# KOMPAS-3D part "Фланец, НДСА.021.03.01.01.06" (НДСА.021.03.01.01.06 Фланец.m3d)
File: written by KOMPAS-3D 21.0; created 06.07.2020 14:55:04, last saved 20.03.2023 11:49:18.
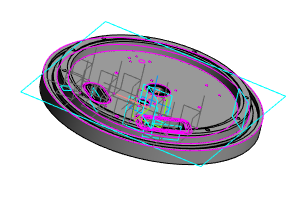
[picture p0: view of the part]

Document properties: Автор: 111; Полное имя файла: C:\Users\korychko\Desktop\PLM\НДСА.021.03.01.01.06 Фланец.m3d

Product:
- Part/product: Фланец  | designation НДСА.021.03.01.01.06
    Материал: АМг2,5 ГОСТ 4784-97 (density 2680 kg/m3)
    Масса: 6.75238
    additional columns: <item xmlns="http://appius.ru/pdm" xmlns:xs="http://www.w3.org/2001/XMLSchema" x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; <item xmlns="http://appius.ru/pdm" xmlns:xs="http://www.w3.org/2001/XMLSchema" x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; <item xmlns="http://appius.ru/pdm" xmlns:xs="http://www.w3.org/2001/XMLSchema" x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; <item xmlns="http://appius.ru/pdm" xmlns:xs="http://www.w3.org/2001/XMLSchema" x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; <item xmlns="http://appius.ru/pdm" xmlns:xs="http://www.w3.org/2001/XMLSchema" x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; <item xmlns="http://appius.ru/pdm" xmlns:xs="http://www.w3.org/2001/XMLSchema" x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; <item xmlns="http://appius.ru/pdm" xmlns:xs="http://www.w3.org/2001/XMLSchema" x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
    source file: НДСА.021.03.01.01.06 Фланец.cdw

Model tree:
1. Эскиз:1
2. Элемент выдавливания:1
     Расстояние 1 = 25
3. Эскиз:3  (with: Элемент выдавливания:1)
4. Элемент выдавливания:3  (with: Элемент выдавливания:1)
     Расстояние 2 = 25
5. Эскиз:4  (with: Элемент выдавливания:1, Элемент выдавливания:3)
6. Элемент выдавливания:4  (with: Элемент выдавливания:1)
     Расстояние 2 = 25
7. Эскиз:6  (with: Элемент выдавливания:1, Элемент выдавливания:3)
8. Элемент выдавливания:5
     Расстояние 2 = 15
9. Условное изображение резьбы:1  (with: Элемент выдавливания:5)  (labels: M4; cil0_24705-2004 coarse)
     Длина резьбы = 15; Шаг резьбы = 0.7; Номинальный диаметр резьбы = 4
10. Подгонка:1  (with: Элемент выдавливания:5)
11. Условное изображение резьбы:2  (with: Элемент выдавливания:5)  (labels: M4; cil0_24705-2004 coarse)
     Длина резьбы = 15; Шаг резьбы = 0.7; Номинальный диаметр резьбы = 4
12. Подгонка:2  (with: Элемент выдавливания:5)
13. Условное изображение резьбы:3  (with: Элемент выдавливания:5)  (labels: M4; cil0_24705-2004 coarse)
     Длина резьбы = 15; Шаг резьбы = 0.7; Номинальный диаметр резьбы = 4
14. Подгонка:3  (with: Элемент выдавливания:5)
15. Условное изображение резьбы:4  (with: Элемент выдавливания:5)  (labels: M4; cil0_24705-2004 coarse)
     Длина резьбы = 15; Шаг резьбы = 0.7; Номинальный диаметр резьбы = 4
16. Подгонка:4  (with: Элемент выдавливания:5)
17. Эскиз:7  (with: Элемент выдавливания:1, Элемент выдавливания:4)
18. Элемент выдавливания:6
     Расстояние 2 = 10
19. Условное изображение резьбы:5  (with: Элемент выдавливания:6)  (labels: M4; cil0_24705-2004 coarse)
     Длина резьбы = 10; Шаг резьбы = 0.7; Номинальный диаметр резьбы = 4
20. Подгонка:5  (with: Элемент выдавливания:6)
21. Смещенная плоскость:1
     Расстояние = 18
22. Эскиз:8  (with: Элемент выдавливания:3)
23. Элемент вращения:2  (with: Элемент выдавливания:3)
     Угол 1 = 360
24. Скругление:3  (with: Элемент вращения:2)
     Радиус = 0.38
25. Скругление:4  (with: Элемент вращения:2)
     Радиус = 0.79
26. Смещенная плоскость:2
     Расстояние = 36
27. Эскиз:9
28. Элемент вращения:3  (with: Элемент выдавливания:4)
     Угол 1 = 360
29. Скругление:5  (with: Элемент вращения:3)
     Радиус = 0.13
30. Скругление:6  (with: Элемент вращения:3)
     Радиус = 0.4
31. Эскиз:10  (with: Элемент выдавливания:1)
32. Элемент выдавливания:7  (with: Элемент выдавливания:1)
     Расстояние 2 = 25
33. Эскиз:11  (with: Элемент выдавливания:1, Элемент выдавливания:7)
34. Элемент выдавливания:8
     Расстояние 2 = 5
35. Смещенная плоскость:3  (with: Элемент выдавливания:7)
     Расстояние = 8.5
36. Эскиз:12  (with: Элемент выдавливания:7)
37. Эскиз:13  (with: Элемент выдавливания:1, Элемент выдавливания:7)
38. Элемент по траектории:1
39. Скругление:7  (with: Элемент по траектории:1)
     Радиус = 0.38
40. Скругление:8  (with: Элемент по траектории:1)
     Радиус = 0.79
41. Эскиз:14  (with: Элемент выдавливания:1)
42. Элемент выдавливания:9  (with: Элемент выдавливания:1)
     Расстояние 2 = 25
43. Эскиз:15  (with: Элемент выдавливания:1, Элемент выдавливания:9)
44. Элемент выдавливания:10
     Расстояние 2 = 5
45. Смещенная плоскость:4  (with: Элемент выдавливания:9)
     Расстояние = 15
46. Эскиз:16  (with: Элемент выдавливания:9)
47. Эскиз:17  (with: Элемент выдавливания:1, Элемент выдавливания:9)
48. Элемент по траектории:2
49. Скругление:9  (with: Элемент по траектории:2)
     Радиус = 0.38
50. Скругление:10  (with: Элемент по траектории:2)
     Радиус = 0.79
51. Эскиз:19  (with: Элемент выдавливания:1, Скругление:3)
52. Элемент выдавливания:12
     Расстояние 2 = 12
53. Условное изображение резьбы:14  (with: Элемент выдавливания:12)  (labels: M6; cil0_24705-2004 coarse)
     Длина резьбы = 12; Шаг резьбы = 1; Номинальный диаметр резьбы = 6
54. Подгонка:14  (with: Элемент выдавливания:12)
55. Условное изображение резьбы:15  (with: Элемент выдавливания:12)  (labels: M6; cil0_24705-2004 coarse)
     Длина резьбы = 12; Шаг резьбы = 1; Номинальный диаметр резьбы = 6
56. Подгонка:15  (with: Элемент выдавливания:12)
57. Эскиз:20  (with: Элемент выдавливания:1, Скругление:3)
58. Элемент выдавливания:13
     Расстояние 2 = 10
59. Условное изображение резьбы:16  (with: Элемент выдавливания:13)  (labels: M5; cil0_24705-2004 coarse)
     Длина резьбы = 10; Шаг резьбы = 0.8; Номинальный диаметр резьбы = 5
60. Подгонка:16  (with: Элемент выдавливания:13)
61. Условное изображение резьбы:17  (with: Элемент выдавливания:13)  (labels: M5; cil0_24705-2004 coarse)
     Длина резьбы = 10; Шаг резьбы = 0.8; Номинальный диаметр резьбы = 5
62. Подгонка:17  (with: Элемент выдавливания:13)
63. Эскиз:21  (with: Элемент выдавливания:1, Элемент выдавливания:12, Элемент выдавливания:13)
64. Элемент выдавливания:14
     Расстояние 2 = 8
65. Условное изображение резьбы:18  (with: Элемент выдавливания:14)  (labels: M3; cil0_24705-2004 coarse)
     Длина резьбы = 8; Шаг резьбы = 0.5; Номинальный диаметр резьбы = 3
66. Подгонка:18  (with: Элемент выдавливания:14)
67. Условное изображение резьбы:19  (with: Элемент выдавливания:14)  (labels: M3; cil0_24705-2004 coarse)
     Длина резьбы = 8; Шаг резьбы = 0.5; Номинальный диаметр резьбы = 3
68. Подгонка:19  (with: Элемент выдавливания:14)
69. Эскиз:22  (with: Элемент выдавливания:1)
70. Элемент выдавливания:15
     Расстояние 2 = 8
71. Условное изображение резьбы:20  (with: Элемент выдавливания:15)  (labels: M4; cil0_24705-2004 coarse)
     Длина резьбы = 8; Шаг резьбы = 0.7; Номинальный диаметр резьбы = 4
72. Подгонка:20  (with: Элемент выдавливания:15)
73. Условное изображение резьбы:21  (with: Элемент выдавливания:15)  (labels: M4; cil0_24705-2004 coarse)
     Длина резьбы = 8; Шаг резьбы = 0.7; Номинальный диаметр резьбы = 4
74. Подгонка:21  (with: Элемент выдавливания:15)
75. Отверстие:10  (with: Элемент выдавливания:5)
     Глубина выреза = 1.8; Диаметр отверстия = 3.24223; Угол конуса дна = 120; Расстояние 1 = 39.2132; Расстояние 2 = 21.2132
76. Отверстие:11  (with: Элемент выдавливания:5)
     Глубина выреза = 1.8; Диаметр отверстия = 3.24223; Угол конуса дна = 120; Расстояние 1 = -3.2132; Расстояние 2 = 21.2132
77. Отверстие:12  (with: Элемент выдавливания:5)
     Глубина выреза = 1.8; Диаметр отверстия = 3.24223; Угол конуса дна = 120; Расстояние 1 = 39.2132; Расстояние 2 = -21.2132
78. Отверстие:13  (with: Элемент выдавливания:5)
     Глубина выреза = 1.8; Диаметр отверстия = 3.24223; Угол конуса дна = 120; Расстояние 1 = -3.2132; Расстояние 2 = -21.2132
79. Отверстие:15  (with: Элемент выдавливания:12)
     Глубина выреза = 3; Диаметр отверстия = 4.91747; Угол конуса дна = 120; Расстояние 1 = 18; Расстояние 2 = 73
80. Отверстие:16  (with: Элемент выдавливания:12)
     Глубина выреза = 3; Диаметр отверстия = 4.91747; Угол конуса дна = 120; Расстояние 1 = 18; Расстояние 2 = -73
81. Отверстие:17  (with: Элемент выдавливания:13)
     Глубина выреза = 3; Диаметр отверстия = 4.13397; Угол конуса дна = 120; Расстояние 1 = 93; Расстояние 2 = 50
82. Отверстие:18  (with: Элемент выдавливания:13)
     Глубина выреза = 3; Диаметр отверстия = 4.13397; Угол конуса дна = 120; Расстояние 1 = 93; Расстояние 2 = -50
83. Отверстие:19  (with: Элемент выдавливания:14)
     Глубина выреза = 1.6; Диаметр отверстия = 2.45873; Угол конуса дна = 120; Расстояние 1 = 93; Расстояние 2 = 73
84. Отверстие:20  (with: Элемент выдавливания:14)
     Глубина выреза = 1.6; Диаметр отверстия = 2.45873; Угол конуса дна = 120; Расстояние 1 = 70; Расстояние 2 = 73
85. Отверстие:21  (with: Элемент выдавливания:15)
     Глубина выреза = 2; Диаметр отверстия = 3.24223; Угол конуса дна = 120; Расстояние 1 = 79.196; Расстояние 2 = 79.196
86. Отверстие:22  (with: Элемент выдавливания:15)
     Глубина выреза = 2; Диаметр отверстия = 3.24223; Угол конуса дна = 120; Расстояние 1 = 79.196; Расстояние 2 = -79.196
87. Эскиз:23  (with: Элемент выдавливания:1, Отверстие:1)
88. Отверстие:23  (with: Элемент выдавливания:1)  (labels: M5)
     Глубина выреза = 14; Диаметр отверстия = 4.13397; Угол конуса дна = 118; Расстояние 1 = 129.904; Расстояние 2 = 75
89. M5  (with: Элемент выдавливания:1)  (labels: cil0_24705-2004 coarse)
     Длина резьбы = 10; Шаг резьбы = 0.8; Номинальный диаметр резьбы = 5
90. Массив по концентрической сетке:3  (with: Отверстие:23)  (labels: M5)  (2 pattern instances)
91. Отверстие:23  (labels: M5)
92. Отверстие:23  (labels: M5)
93. Отверстие:23  (labels: M5)
94. Отверстие:23  (labels: M5)
95. Эскиз:25  (with: Элемент выдавливания:1, Элемент выдавливания:6)
96. ЛСК:2  (with: Плоскость XY, Плоскость ZX, Плоскость ZY, Ось X, Ось Y, Ось Z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)
     Ось X. Z = 1; Ось Y. X = 1; Ось Z. Y = 1; Координата X = 15.5885; Координата Y = 27; Координата Z = 25; Точка начала. Х = 15.5885; Точка начала. Y = 27; Точка начала. Z = 25
97. Эскиз:26
98. Элемент вращения:4
     Угол 1 = 360
99. Смещенная плоскость:5  (with: Элемент выдавливания:1)
100. Отверстие М4x12-14
101. Массив по концентрической сетке:4  (with: Элемент вращения:4)  (2 pattern instances)
102. Элемент вращения:4
103. Условное изображение резьбы:22  (with: Элемент вращения:4, Подгонка:1)  (labels: M4; cil0_24705-2004 coarse)
     Длина резьбы = 12; Шаг резьбы = 0.7; Номинальный диаметр резьбы = 4
104. Условное изображение резьбы:23  (with: Элемент вращения:4, Подгонка:2)  (labels: M4; cil0_24705-2004 coarse)
     Длина резьбы = 12; Шаг резьбы = 0.7; Номинальный диаметр резьбы = 4
105. Эскиз:35  (with: Элемент выдавливания:1, Элемент выдавливания:10)
106. ЛСК:9  (with: Плоскость XY, Плоскость ZX, Плоскость ZY, Ось X, Ось Y, Ось Z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)
     Ось X. Z = 1; Ось Y. X = 1; Ось Z. Y = 1; Координата X = -72.8442; Координата Y = 104.032; Координата Z = 25; Точка начала. Х = -72.8442; Точка начала. Y = 104.032; Точка начала. Z = 25
107. Эскиз:36
108. Элемент вращения:7
     Угол 1 = 360
109. Смещенная плоскость:8  (with: Элемент выдавливания:1)
110. Условное изображение резьбы:24  (with: Элемент вращения:7, Подгонка:3)  (labels: 4x0,699999)
     Длина резьбы = 15; Шаг резьбы = 0.7; Номинальный диаметр резьбы = 4
111. Отверстие М4x15-17
112. Эскиз:38  (with: Элемент выдавливания:1, Элемент выдавливания:10)
113. ЛСК:11  (with: Плоскость XY, Плоскость ZX, Плоскость ZY, Ось X, Ось Y, Ось Z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)
     Ось X. Z = 1; Ось Y. X = 1; Ось Z. Y = 1; Координата X = -11.2387; Координата Y = 109.325; Координата Z = 25; Точка начала. Х = -11.2387; Точка начала. Y = 109.325; Точка начала. Z = 25
114. Эскиз:39
115. Элемент вращения:8
     Угол 1 = 360
116. Смещенная плоскость:9  (with: Элемент выдавливания:1)
117. Условное изображение резьбы:25  (with: Элемент вращения:8, Подгонка:4)  (labels: 4x0,699999)
     Длина резьбы = 15; Шаг резьбы = 0.7; Номинальный диаметр резьбы = 4
118. Отверстие М4x15-17 (1)
119. Эскиз:41  (with: Элемент выдавливания:1, Элемент выдавливания:10)
120. ЛСК:13  (with: Плоскость XY, Плоскость ZX, Плоскость ZY, Ось X, Ось Y, Ось Z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)
     Ось X. Z = 1; Ось Y. X = 1; Ось Z. Y = 1; Координата X = -98.888; Координата Y = 47.9523; Координата Z = 25; Точка начала. Х = -98.888; Точка начала. Y = 47.9523; Точка начала. Z = 25
121. Эскиз:42
122. Элемент вращения:9
     Угол 1 = 360
123. Смещенная плоскость:10  (with: Элемент выдавливания:1)
124. Условное изображение резьбы:26  (with: Элемент вращения:9, Подгонка:5)  (labels: 4x0,699999)
     Длина резьбы = 15; Шаг резьбы = 0.7; Номинальный диаметр резьбы = 4
125. Отверстие М4x15-17 (2)
126. Эскиз:44  (with: Элемент выдавливания:1, Элемент выдавливания:10)
127. ЛСК:15  (with: Плоскость XY, Плоскость ZX, Плоскость ZY, Ось X, Ось Y, Ось Z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)
     Ось X. Z = 1; Ось Y. X = 1; Ось Z. Y = 1; Координата X = -37.2825; Координата Y = 53.2449; Координата Z = 25; Точка начала. Х = -37.2825; Точка начала. Y = 53.2449; Точка начала. Z = 25
128. Эскиз:45
129. Элемент вращения:10
     Угол 1 = 360
130. Смещенная плоскость:11  (with: Элемент выдавливания:1)
131. Условное изображение резьбы:27  (with: Элемент вращения:10)  (labels: 4x0,699999)
     Длина резьбы = 15; Шаг резьбы = 0.7; Номинальный диаметр резьбы = 4
132. Подгонка:6
133. Отверстие М4x15-17 (3)
134. Эскиз:48  (with: Элемент выдавливания:1, Элемент выдавливания:8)
135. ЛСК:18  (with: Плоскость XY, Плоскость ZX, Плоскость ZY, Ось X, Ось Y, Ось Z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)
     Ось X. Z = 1; Ось Y. X = 1; Ось Z. Y = 1; Координата X = 38.7495; Координата Y = 95.318; Координата Z = 25; Точка начала. Х = 38.7495; Точка начала. Y = 95.318; Точка начала. Z = 25
136. Эскиз:49
137. Элемент вращения:11
     Угол 1 = 360
138. Смещенная плоскость:12  (with: Элемент выдавливания:1)
139. Условное изображение резьбы:28  (with: Элемент вращения:11)  (labels: 4x0,699999)
     Длина резьбы = 15; Шаг резьбы = 0.7; Номинальный диаметр резьбы = 4
140. Подгонка:7
141. Отверстие М4x15-17 (4)
142. Эскиз:51  (with: Элемент выдавливания:1, Элемент выдавливания:8)
143. ЛСК:20  (with: Плоскость XY, Плоскость ZX, Плоскость ZY, Ось X, Ось Y, Ось Z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)
     Ось X. Z = 1; Ось Y. X = 1; Ось Z. Y = 1; Координата X = 87.1863; Координата Y = 87.1863; Координата Z = 25; Точка начала. Х = 87.1863; Точка начала. Y = 87.1863; Точка начала. Z = 25
144. Эскиз:52
145. Элемент вращения:12
     Угол 1 = 360
146. Смещенная плоскость:13  (with: Элемент выдавливания:1)
147. Условное изображение резьбы:29  (with: Элемент вращения:12)  (labels: 4x0,699999)
     Длина резьбы = 15; Шаг резьбы = 0.7; Номинальный диаметр резьбы = 4
148. Подгонка:8
149. Отверстие М4x15-17 (5)
150. Эскиз:54  (with: Элемент выдавливания:1, Элемент выдавливания:8)
151. ЛСК:22  (with: Плоскость XY, Плоскость ZX, Плоскость ZY, Ось X, Ось Y, Ось Z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)
     Ось X. Z = 1; Ось Y. X = 1; Ось Z. Y = 1; Координата X = 46.8812; Координата Y = 46.8812; Координата Z = 25; Точка начала. Х = 46.8812; Точка начала. Y = 46.8812; Точка начала. Z = 25
152. Эскиз:55
153. Элемент вращения:13
     Угол 1 = 360
154. Смещенная плоскость:14  (with: Элемент выдавливания:1)
155. Условное изображение резьбы:30  (with: Элемент вращения:13)  (labels: 4x0,699999)
     Длина резьбы = 15; Шаг резьбы = 0.7; Номинальный диаметр резьбы = 4
156. Подгонка:9
157. Отверстие М4x15-17 (6)
158. Эскиз:57  (with: Элемент выдавливания:1, Элемент выдавливания:8)
159. ЛСК:24  (with: Плоскость XY, Плоскость ZX, Плоскость ZY, Ось X, Ось Y, Ось Z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)
     Ось X. Z = 1; Ось Y. X = 1; Ось Z. Y = 1; Координата X = 95.318; Координата Y = 38.7495; Координата Z = 25; Точка начала. Х = 95.318; Точка начала. Y = 38.7495; Точка начала. Z = 25
160. Эскиз:58
161. Элемент вращения:14
     Угол 1 = 360
162. Смещенная плоскость:15  (with: Элемент выдавливания:1)
163. Условное изображение резьбы:31  (with: Элемент вращения:14)  (labels: 4x0,699999)
     Длина резьбы = 15; Шаг резьбы = 0.7; Номинальный диаметр резьбы = 4
164. Подгонка:10
165. Отверстие М4x15-17 (7)
166. Эскиз:59  (with: Элемент выдавливания:1)
167. Элемент выдавливания:16
     Расстояние 1 = 18
168. Эскиз:60  (with: Элемент выдавливания:16)
169. Отверстие:24  (with: Элемент выдавливания:16)  (labels: M8)
     Глубина выреза = 18; Диаметр отверстия = 6.64684; Угол конуса дна = 118; Расстояние 1 = -145
170. M8  (with: Элемент выдавливания:16)  (labels: cil0_24705-2004 coarse)
     Длина резьбы = 15; Шаг резьбы = 1.25; Номинальный диаметр резьбы = 8
171. Массив по концентрической сетке:5  (with: Отверстие:24)  (labels: M8)  (2 pattern instances)
172. Отверстие:24  (labels: M8)
173. Отверстие:24  (labels: M8)
174. Отверстие:24  (labels: M8)
175. Отверстие:24  (labels: M8)
176. Отверстие:24  (labels: M8)
177. Отверстие:24  (labels: M8)
178. Отверстие:24  (labels: M8)
179. Отверстие:24  (labels: M8)
180. Отверстие:24  (labels: M8)
181. Отверстие:24  (labels: M8)
182. Эскиз:61  (with: Элемент выдавливания:16)
183. Элемент выдавливания:17
     Расстояние 2 = 2
184. Фаска:1  (with: Элемент выдавливания:16)
     Угол = 75; Длина 1 = 1; Длина 2 = 3.73205
185. Эскиз:62  (with: Элемент выдавливания:1, Элемент выдавливания:5, Элемент выдавливания:6, Скругление:3, Скругление:5, Скругление:7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)
186. Эскиз:63  (with: Элемент выдавливания:1, Скругление:10, Элемент выдавливания:9)
187. Эскиз:65  (with: Элемент выдавливания:1)
188. Эскиз:66
189. Элемент вращения:15
     Угол 1 = 360
190. Скругление:11  (with: Элемент вращения:15)
     Радиус = 0.2
191. Скругление:12  (with: Элемент вращения:15)
     Радиус = 0.8
192. Плоскость под углом:1
     Угол = 45
193. Смещенная плоскость:16
     Расстояние = 153
194. Отверстие:30  (with: Элемент выдавливания:16)
     Глубина выреза = 8; Диаметр отверстия = 6; Угол конуса дна = 118; Угол 1 = 45; Расстояние 2 = 10
195. Нормальная плоскость:1  (with: Отверстие:30)
196. Отверстие:31  (with: Элемент выдавливания:16, Фаска:1, Отверстие:30)
     Глубина выреза = 20; Диаметр отверстия = 2; Угол конуса дна = 118; Угол 1 = 45; Расстояние 2 = 6.26795
197. Фаска:3  (with: Отверстие:30)
     Угол = 45; Длина 1 = 0.5; Длина 2 = 0.5
198. Фаска:4  (with: Отверстие:31)  (labels: АМг2,5 ГОСТ 4784-97)
     Угол = 45; Длина 1 = 0.2; Длина 2 = 0.2

Referenced files in C:\Users\korychko\Desktop\PLM\: НДСА.021.03.01.00.00 Столик.a3d
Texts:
  KTE.LIST=N.JCFQmPcnMVtYB9e4EPvb
  Edge1
  Edge2
  Центр круглого ребра
  НДСА.021.03.01.01.06
  Неподвижный вал основания
  Шаг 1
  Режим 1
  Шаг 2
  Режим 2
  Шаг по оси
  Номер 1
  Номер 2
